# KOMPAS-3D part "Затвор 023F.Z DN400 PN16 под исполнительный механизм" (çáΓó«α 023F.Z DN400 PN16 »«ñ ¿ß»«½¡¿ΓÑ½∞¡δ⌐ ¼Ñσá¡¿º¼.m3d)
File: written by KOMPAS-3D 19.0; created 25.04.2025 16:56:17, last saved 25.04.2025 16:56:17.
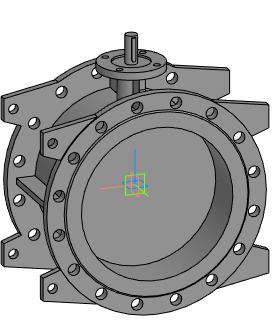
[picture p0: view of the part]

Document properties: Автор: Евгений; Полное имя файла: E:\Dendor Работа Сачек\3D для проекитирвщиков\1.7 Тип 023F.Z Затвор дисковый поворотный фланцевый с двумя эксцентриками\stp_Тип 023F.Z. Затвор под исполн. механизм\Затвор 023F.Z DN400 PN16 под исполнительный механизм.m3d

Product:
- Part/product: Затвор 023F.Z DN400 PN16 под исполнительный механизм

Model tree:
1. Операция без истории:1  (labels: Затвор 023F.Z DN400 PN16 под исполнительный механизм)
